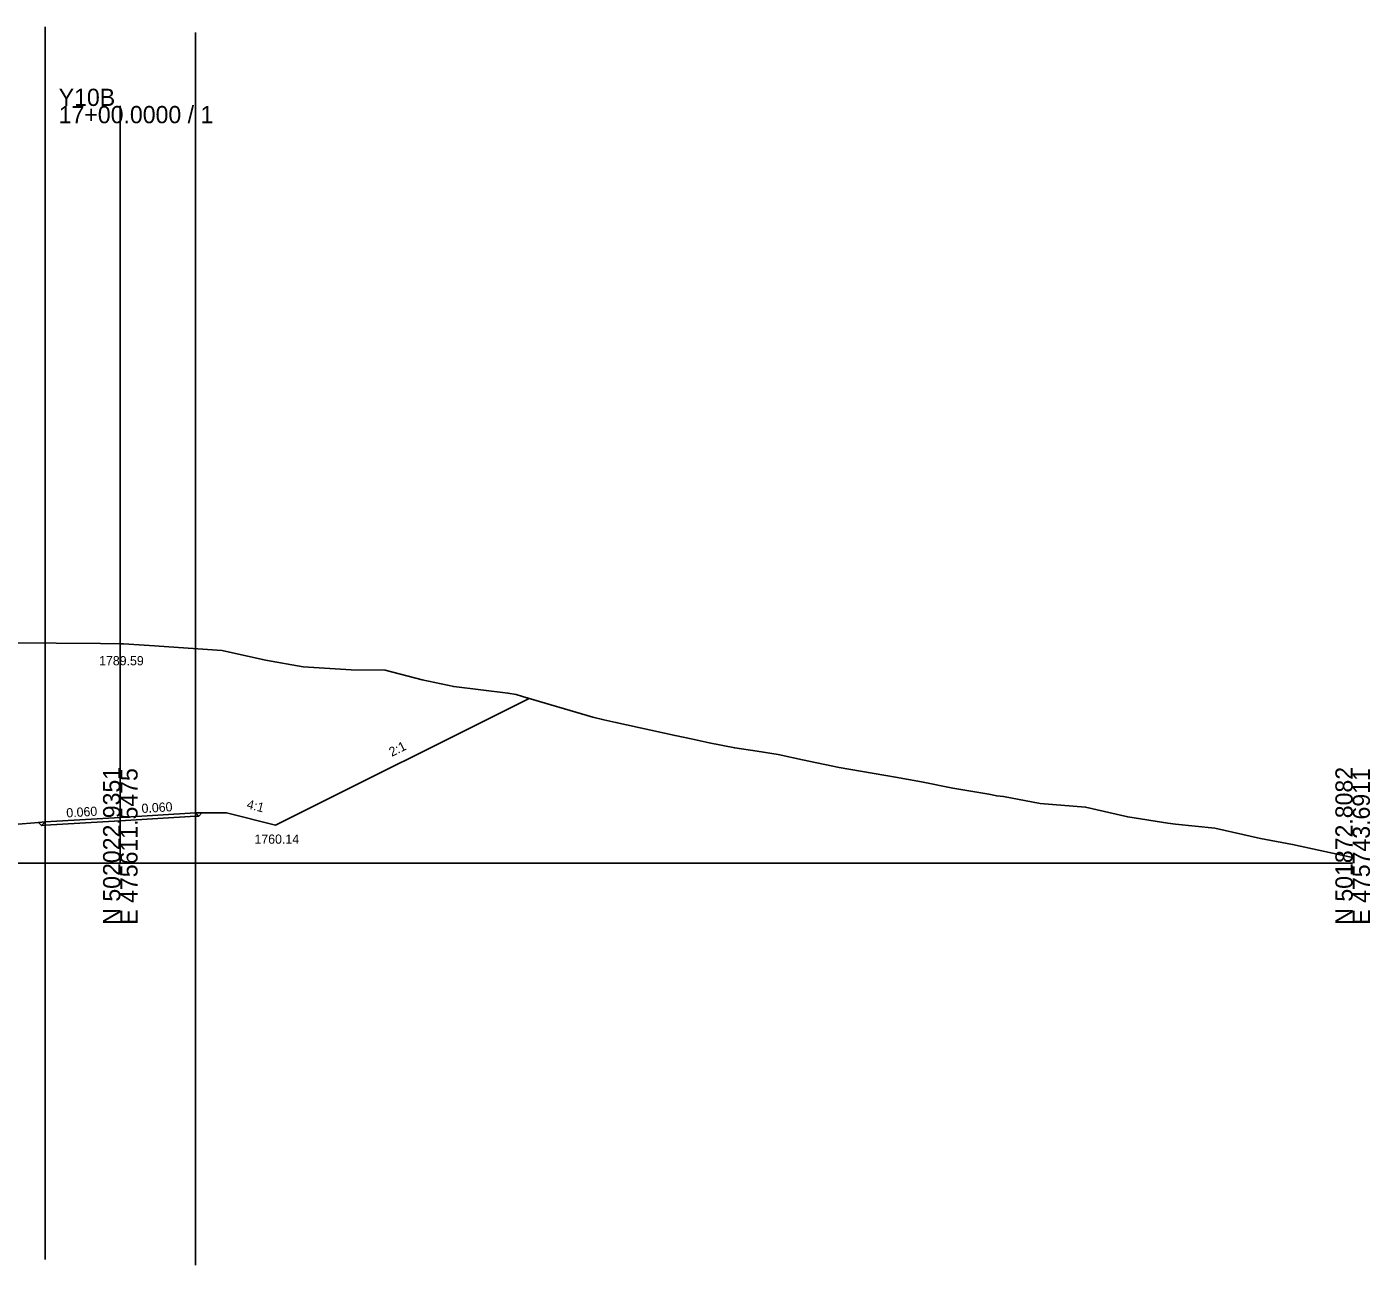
# Model space of a CAD drawing. Extents: x -26 to 1803, y -10 to 9558.
# Drawn here: x 184.8 to 402.8, y 6934.8 to 7135.7 of the extents above; entities that cross this region are included whole.
import ezdxf

# ---------------------------------------------------------------- set-up
doc = ezdxf.new("R2010")
doc.units = 0
for name, color, linetype in [('Exist Cross Section Cell', 7, 'Continuous'), ('Exist XS Center Line Elevation Label', 7, 'Continuous'), ('Exist XS Ground Line', 7, 'Continuous'), ('Prop XS Ditch Slope Text', 7, 'Continuous'), ('Prop XS Ditch Standard Text', 7, 'Continuous'), ('Prop XS Dump Level', 7, 'Continuous'), ('Prop XS Earthwork Shape', 7, 'Continuous'), ('Prop XS EOT Tick Mark', 7, 'Continuous'), ('Prop XS Finish Grade', 7, 'Continuous'), ('Prop XS Finish Grade Earthwork', 7, 'Continuous'), ('Prop XS Finish Grade Pavement', 7, 'Continuous'), ('Prop XS Hydro Typical Ditch Data', 7, 'Continuous'), ('Prop XS Pvmt Edge Slope', 7, 'Continuous'), ('Prop XS SE Text', 7, 'Continuous'), ('Prop XS Shoulder Borrow Shape', 7, 'Continuous'), ('Prop XS Side Slope Text', 7, 'Continuous'), ('Prop XS Subgrade Earthwork', 7, 'Continuous'), ('Scratch_Level_2', 7, 'Continuous')]:
    doc.layers.add(name, color=color, linetype=linetype)

msp = doc.modelspace()

# ---------------------------------------------------------------- linework, layer by layer
at = {"layer": 'Exist Cross Section Cell'}
for p, q in [((200, 7000), (200, 7122.85)), ((0, 7000), (200, 7000)), ((200, 7000), (400, 7000))]:
    msp.add_line(p, q, dxfattribs=at)
at = {"layer": 'Exist XS Ground Line'}
msp.add_lwpolyline([(183.44, 7035.72), (189.59, 7035.67), (196.76, 7035.62), (200, 7035.59), (200.49, 7035.58), (204.72, 7035.29), (216.54, 7034.47), (223.57, 7032.92), (229.7, 7031.87), (237.47, 7031.38), (243.01, 7031.28), (248.97, 7029.75), (254.12, 7028.65), (262.9, 7027.59), (264.27, 7027.36), (265.28, 7027.04), (276.71, 7023.66), (278.45, 7023.27), (280.42, 7022.84), (290.03, 7020.7), (292.62, 7020.15), (295.56, 7019.52), (299.71, 7018.69), (303.36, 7018.16), (306.79, 7017.6), (310.69, 7016.78), (316.68, 7015.53), (325.83, 7013.93), (330.01, 7013.17), (335.14, 7012.15), (340.97, 7011.21), (342.23, 7010.9), (343.33, 7010.78), (349.31, 7009.69), (356.66, 7009.08), (363.49, 7007.49), (369.98, 7006.5), (371.25, 7006.32), (377.66, 7005.65), (385.05, 7004), (390.26, 7003.01), (400, 7000.92)], dxfattribs=at)
at = {"layer": 'Prop XS Dump Level'}
for p, q in [((187.79, 7006.68), (200, 7007.41)), ((200, 7007.41), (212.21, 7008.14))]:
    msp.add_line(p, q, dxfattribs=at)
at = {"layer": 'Prop XS Earthwork Shape'}
msp.add_lwpolyline([(183.44, 7035.72), (189.59, 7035.67), (196.76, 7035.62), (200, 7035.59), (200.49, 7035.58), (204.72, 7035.29), (216.54, 7034.47), (223.57, 7032.92), (229.7, 7031.87), (237.47, 7031.38), (243.01, 7031.28), (248.97, 7029.75), (254.12, 7028.65), (262.9, 7027.59), (264.27, 7027.36), (265.28, 7027.04), (266.37, 7026.72), (225.21, 7006.14), (217.21, 7008.14), (213.23, 7008.14), (212.72, 7007.63), (212.21, 7007.6), (200, 7006.87), (187.79, 7006.14), (187.21, 7006.1), (186.72, 7006.59), (182.79, 7006.28)], dxfattribs=at)
at = {"layer": 'Prop XS EOT Tick Mark'}
for p, q in [((212.21, 7008.14), (212.21, 7009.14)), ((187.79, 7006.68), (187.79, 7007.68))]:
    msp.add_line(p, q, dxfattribs=at)
at = {"layer": 'Prop XS Finish Grade'}
for p, q in [((212.21, 7008.14), (213.23, 7008.14)), ((187.79, 7006.68), (186.72, 7006.59))]:
    msp.add_line(p, q, dxfattribs=at)
at = {"layer": 'Prop XS Finish Grade Earthwork'}
for p, q in [((225.21, 7006.14), (266.37, 7026.72)), ((213.23, 7008.14), (217.21, 7008.14)), ((217.21, 7008.14), (225.21, 7006.14)), ((186.72, 7006.59), (182.79, 7006.28))]:
    msp.add_line(p, q, dxfattribs=at)
at = {"layer": 'Prop XS Finish Grade Pavement'}
for p, q in [((187.79, 7006.68), (200, 7007.41)), ((200, 7007.41), (212.21, 7008.14))]:
    msp.add_line(p, q, dxfattribs=at)
at = {"layer": 'Prop XS Hydro Typical Ditch Data'}
for p, q in [((225.21, 7006.14), (266.37, 7026.72)), ((217.21, 7008.14), (225.21, 7006.14))]:
    msp.add_line(p, q, dxfattribs=at)
at = {"layer": 'Prop XS Pvmt Edge Slope'}
for p, q in [((212.21, 7008.14), (212.72, 7007.63)), ((187.79, 7006.68), (187.21, 7006.1))]:
    msp.add_line(p, q, dxfattribs=at)
at = {"layer": 'Prop XS Shoulder Borrow Shape'}
for points in [[(212.21, 7008.14), (213.23, 7008.14), (212.72, 7007.63)], [(187.79, 7006.68), (186.72, 7006.59), (187.21, 7006.1)]]:
    msp.add_lwpolyline(points, close=True, dxfattribs=at)
at = {"layer": 'Prop XS Subgrade Earthwork'}
for p, q in [((200, 7006.87), (187.79, 7006.14)), ((212.21, 7007.6), (200, 7006.87)), ((212.21, 7007.6), (212.72, 7007.63)), ((212.72, 7007.63), (213.23, 7008.14)), ((187.21, 7006.1), (186.72, 7006.59)), ((187.79, 7006.14), (187.21, 7006.1))]:
    msp.add_line(p, q, dxfattribs=at)
at = {"layer": 'Scratch_Level_2'}
for p, q in [((187.79, 7135.68), (187.79, 6935.68)), ((212.21, 7134.77), (212.21, 6934.77))]:
    msp.add_line(p, q, dxfattribs=at)

# ---------------------------------------------------------------- texts
at = {"layer": 'Exist Cross Section Cell'}
for s, p in [('Y10B', (190, 7122.85)), ('17+00.0000 / 1', (190, 7120.05))]:
    msp.add_text(s, height=2.8, dxfattribs=at).set_placement(p)
for s, p in [('N 502022.9351', (200, 6990)), ('E 475611.5475', (202.8, 6990)), ('N 501872.8082', (400, 6990)), ('E 475743.6911', (402.8, 6990))]:
    msp.add_text(s, height=2.8, rotation=90, dxfattribs=at).set_placement(p)
at = {"layer": 'Exist XS Center Line Elevation Label'}
msp.add_text('1789.59', height=1.5, dxfattribs=at).set_placement((196.55, 7032.09))
at = {"layer": 'Prop XS Ditch Slope Text'}
msp.add_text('4:1', height=1.5, rotation=345.9676, dxfattribs=at).set_placement((220.42, 7008.89))
at = {"layer": 'Prop XS Ditch Standard Text'}
msp.add_text('1760.14', height=1.5, dxfattribs=at).set_placement((221.77, 7003.14))
at = {"layer": 'Prop XS Dump Level'}
msp.add_text('Case1', height=0.04, dxfattribs=at).set_placement((217.21, 7008.1))
at = {"layer": 'Prop XS SE Text'}
for p in [(191.28, 7007.39), (203.49, 7008.12)]:
    msp.add_text('0.060', height=1.5, rotation=3.4336, dxfattribs=at).set_placement(p)
at = {"layer": 'Prop XS Side Slope Text'}
msp.add_text('2:1', height=1.5, rotation=26.5584, dxfattribs=at).set_placement((244.06, 7017.24))

doc.saveas('drawing.dxf')
